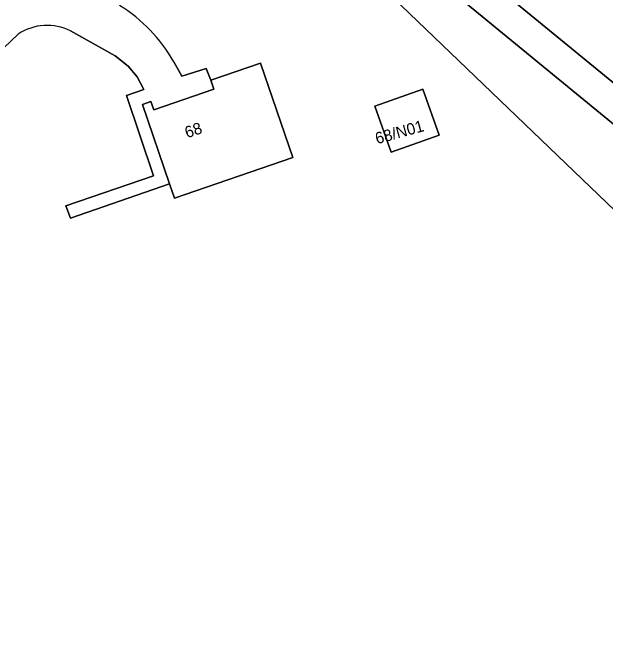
# Model space of a CAD drawing. Extents: x 162417 to 163722, y 384268 to 385417.
# Drawn here: x 163351.6 to 163403.1, y 384814.8 to 384869.2 of the extents above; entities that cross this region are included whole.
import ezdxf

# ---------------------------------------------------------------- set-up
doc = ezdxf.new("R2010")
doc.units = 0
for name, color, linetype in [('IMGEO_Erf', 7, 'Continuous'), ('IMGEO_Loofbos', 7, 'Continuous'), ('IMGEO_Pand', 7, 'Continuous'), ('IMGEO_Pand_nummerreeks', 7, 'Continuous'), ('IMGEO_Rijbaan_lokaal_open', 7, 'Continuous'), ('IMGEO_Voetpad_open', 7, 'Continuous')]:
    doc.layers.add(name, color=color, linetype=linetype)

msp = doc.modelspace()

# ---------------------------------------------------------------- linework, layer by layer
at = {"layer": 'IMGEO_Erf'}
for points in [[(163478.968, 384778.944), (163452.807, 384811.328), (163449.552, 384814.496), (163444.744, 384812.832), (163371.736, 384882.911), (163368.168, 384880.503), (163366.653, 384879.471), (163363.837, 384877.552), (163359.249, 384874.08)], [(163365.587, 384864.936), (163366.302, 384863.683), (163368.413, 384864.364), (163368.799, 384863.337), (163373.132, 384864.82), (163375.942, 384856.61), (163365.646, 384853.085), (163365.216, 384854.34), (163356.607, 384851.355), (163356.211, 384852.406), (163363.819, 384855.025), (163361.467, 384861.993), (163362.992, 384862.532), (163362.415, 384863.614), (163361.637, 384864.562), (163360.503, 384865.462), (163356.619, 384867.614)], [(163352.08, 384867.341), (163333.129, 384849.312)]]:
    msp.add_lwpolyline(points, dxfattribs=at)
msp.add_lwpolyline([(163388.65, 384858.56), (163384.467, 384857.072), (163383.045, 384861.069), (163387.228, 384862.557)], close=True, dxfattribs=at)
for centre, radius, start, end in [((163353.586, 384858.101), 13.811, 29.6625, 58.1302), ((163354.583, 384863.601), 4.5, 63.0928, 123.7911)]:
    msp.add_arc(centre, radius, start, end, dxfattribs=at)
at = {"layer": 'IMGEO_Loofbos'}
for points in [[(163404.422, 384858.994), (163383.225, 384876.4), (163378.166, 384887.357), (163371.736, 384882.911), (163444.744, 384812.832), (163449.552, 384814.496), (163441.59, 384822.244), (163437.759, 384821.38), (163413.902, 384849.546)], [(163392.196, 384872.647), (163408.421, 384859.297), (163410.514, 384857.379), (163414.147, 384853.364), (163438.619, 384824.336), (163442.822, 384825.228), (163444.598, 384823.469), (163448.899, 384826.989), (163448.546, 384827.421), (163446.26, 384830.213), (163406.766, 384879.335), (163392.734, 384873.707), (163392.106, 384873.165)]]:
    msp.add_lwpolyline(points, dxfattribs=at)
at = {"layer": 'IMGEO_Pand'}
for points in [[(163365.646, 384853.085), (163375.942, 384856.61), (163373.132, 384864.82), (163368.799, 384863.337), (163369.07, 384862.545), (163363.851, 384860.759), (163363.603, 384861.483), (163362.859, 384861.228), (163365.216, 384854.34)], [(163388.65, 384858.56), (163387.228, 384862.557), (163383.045, 384861.069), (163384.467, 384857.072)]]:
    msp.add_lwpolyline(points, close=True, dxfattribs=at)
at = {"layer": 'IMGEO_Rijbaan_lokaal_open'}
for points in [[(163356.619, 384867.614), (163360.503, 384865.462), (163361.637, 384864.562), (163362.415, 384863.614), (163362.992, 384862.532), (163361.467, 384861.993), (163363.819, 384855.025), (163356.211, 384852.406), (163356.607, 384851.355), (163365.216, 384854.34), (163362.859, 384861.228), (163363.603, 384861.483), (163363.851, 384860.759), (163369.07, 384862.545), (163368.799, 384863.337), (163368.413, 384864.364), (163366.302, 384863.683), (163365.587, 384864.936)], [(163333.129, 384849.312), (163352.08, 384867.341)]]:
    msp.add_lwpolyline(points, dxfattribs=at)
for centre, radius, start, end in [((163353.586, 384858.101), 13.811, 29.6625, 58.1302), ((163354.583, 384863.601), 4.5, 63.0928, 123.7911)]:
    msp.add_arc(centre, radius, start, end, dxfattribs=at)
at = {"layer": 'IMGEO_Voetpad_open'}
for points in [[(163414.147, 384853.364), (163410.514, 384857.379), (163408.421, 384859.297), (163392.196, 384872.647), (163388.512, 384875.738), (163385.472, 384878.291), (163380.909, 384888.238), (163379.128, 384892.265), (163374.727, 384900.875), (163364.022, 384920.643), (163344.699, 384957.814)], [(163347.204, 384946.37), (163360.118, 384921.532), (163369.878, 384904.051), (163377.046, 384890.814), (163378.166, 384887.357), (163383.225, 384876.4), (163404.422, 384858.994)]]:
    msp.add_lwpolyline(points, dxfattribs=at)

# ---------------------------------------------------------------- texts
at = {"layer": 'IMGEO_Pand_nummerreeks'}
for s, rotation, p in [('68', 18.8915, (163366.743, 384858.281)), ('68/N01', 15.5241, (163383.252, 384857.768))]:
    msp.add_text(s, height=1, rotation=rotation, dxfattribs=at).set_placement(p)

doc.saveas('drawing.dxf')
